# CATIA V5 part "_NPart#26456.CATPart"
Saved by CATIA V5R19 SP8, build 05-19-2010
Part number: U taraudé
Revision: ANY
Definition: UNKNOWN
Nomenclature: U taraudé
Source: Unknown
Bounding box of the stored display mesh (mm): x -45.282 to -34.282, y 20.868 to 32.868, z 0 to 10
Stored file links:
  D:\Documents\1_Travail\1 - ac-limoges.fr\ac-limoges.fr\Emmanuel Maynard - STI2D_Turgot\2 -2I2D\2_SEQUENCE_Serrure_Biométrique\5-Spé_ITEC\Serrure_Bio_Eleve\_NPart#26456.CATPart
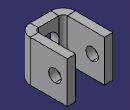
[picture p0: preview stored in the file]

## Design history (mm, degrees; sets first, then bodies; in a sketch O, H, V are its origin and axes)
Body1 "Enlèv. mat.-Extru.3" (main body)
  Solid1: solid without history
